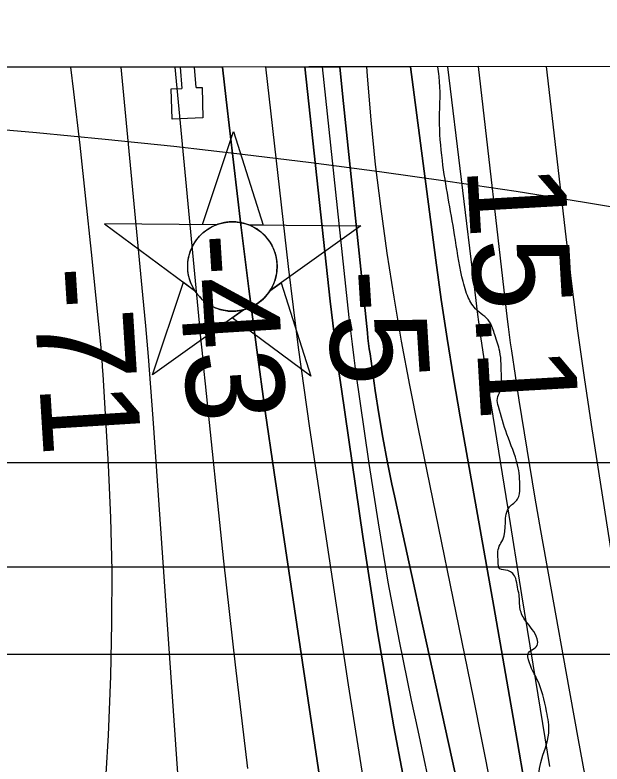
# Model space of a CAD drawing. Extents: x 3313447 to 3351316, y 703786 to 729172.
# Drawn here: x 3324497 to 3324898, y 726885 to 727397 of the extents above; entities that cross this region are included whole.
import ezdxf

# ---------------------------------------------------------------- set-up
doc = ezdxf.new("R2010")
doc.units = 0
for name, color, linetype in [('V-CHAN-DOCK', 7, 'Continuous'), ('V-CHAN-NAID', 7, 'Continuous'), ('V-GRID-FRAM', 7, 'Continuous'), ('V-RIVR-EDGE', 7, 'Continuous'), ('V-RIVR-RANG', 7, 'Continuous'), ('V-TOPO-DPTH', 7, 'Continuous'), ('V-TOPO-MAJR', 7, 'Continuous'), ('V-TOPO-MINR', 7, 'Continuous'), ('V-TOPO-WATR', 7, 'Continuous'), ('V-UTIL-LINE', 7, 'Continuous')]:
    doc.layers.add(name, color=color, linetype=linetype)

msp = doc.modelspace()

# ---------------------------------------------------------------- linework, layer by layer
at = {"layer": 'V-CHAN-DOCK'}
for p, q in [((3324610.23, 727361.24), (3324611.3, 727346.68)), ((3324621.03, 727347.18), (3324619.99, 727361.25)), ((3324604.09, 727346.31), (3324611.3, 727346.68)), ((3324604.6, 727325.6), (3324604.09, 727346.31)), ((3324621.03, 727347.18), (3324625.08, 727347.38)), ((3324625.08, 727347.38), (3324625.59, 727326.67)), ((3324625.59, 727326.67), (3324604.6, 727325.6))]:
    msp.add_line(p, q, dxfattribs=at)
at = {"layer": 'V-CHAN-NAID'}
for points in [[(3324634.94, 727253.57), (3324625.36, 727253.63), (3324646.48, 727317.12), (3324666.71, 727253.34), (3324657.12, 727253.41), (3324655.54, 727253.99), (3324653.45, 727254.61), (3324651.41, 727255.06), (3324649.37, 727255.37), (3324648.21, 727255.48), (3324646.67, 727255.56), (3324644.95, 727255.56), (3324643.58, 727255.49), (3324641.67, 727255.29), (3324640.31, 727255.07), (3324638.52, 727254.68), (3324636.99, 727254.26), (3324635.96, 727253.93)], [(3324634.94, 727253.57), (3324558.45, 727254.11), (3324620.02, 727208.71), (3324618.91, 727210.62), (3324618.1, 727212.25), (3324617.27, 727214.21), (3324616.57, 727216.27), (3324616.21, 727217.59), (3324615.85, 727219.22), (3324615.6, 727220.66), (3324615.42, 727222.26), (3324615.31, 727224), (3324615.3, 727225.58), (3324615.4, 727227.65), (3324615.59, 727229.27), (3324615.98, 727231.47), (3324616.46, 727233.39), (3324617.06, 727235.28), (3324617.72, 727236.96), (3324618.44, 727238.55), (3324619.26, 727240.08), (3324620.32, 727241.82), (3324621.35, 727243.29), (3324622.35, 727244.56), (3324623.35, 727245.71), (3324624.66, 727247.04), (3324625.71, 727248.01), (3324627.43, 727249.4), (3324628.64, 727250.27), (3324630.33, 727251.34), (3324632.06, 727252.29), (3324633.5, 727252.97)], [(3324657.12, 727253.41), (3324733.61, 727252.87), (3324671.41, 727208.34), (3324672.32, 727209.83), (3324673.3, 727211.68), (3324674.01, 727213.26), (3324674.75, 727215.22), (3324675.3, 727217), (3324675.7, 727218.64), (3324676.06, 727220.65), (3324676.24, 727222.23), (3324676.37, 727224.43), (3324676.34, 727226.49), (3324676.15, 727228.71), (3324675.88, 727230.47), (3324675.39, 727232.7), (3324674.75, 727234.84), (3324674, 727236.83), (3324673.35, 727238.27), (3324672.35, 727240.19), (3324671.28, 727241.91), (3324670.07, 727243.61), (3324668.81, 727245.15), (3324667.54, 727246.51), (3324665.91, 727248.05), (3324664.16, 727249.46), (3324662.48, 727250.64), (3324660.59, 727251.77), (3324659.12, 727252.53)], [(3324653.38, 727195.44), (3324591.18, 727150.92), (3324612.3, 727214.4), (3324620.02, 727208.71), (3324620.65, 727207.74), (3324622.04, 727205.89), (3324623.25, 727204.47), (3324624.72, 727202.97), (3324626.1, 727201.72), (3324627.56, 727200.56), (3324628.96, 727199.57), (3324630.64, 727198.54), (3324632.35, 727197.63), (3324634.14, 727196.81), (3324635.59, 727196.26), (3324637.22, 727195.73), (3324639.44, 727195.17), (3324640.98, 727194.88), (3324643, 727194.62), (3324644.54, 727194.52), (3324646.4, 727194.5), (3324648.09, 727194.57), (3324649.8, 727194.75), (3324651.7, 727195.06)], [(3324671.41, 727208.34), (3324679.21, 727213.92), (3324699.43, 727150.15), (3324645.58, 727189.86), (3324653.38, 727195.44), (3324655.04, 727195.91), (3324656.66, 727196.47), (3324658.81, 727197.39), (3324660.55, 727198.27), (3324662.42, 727199.39), (3324664.15, 727200.6), (3324665.71, 727201.84), (3324666.99, 727203.01), (3324668.38, 727204.43), (3324669.58, 727205.83), (3324670.7, 727207.3)]]:
    msp.add_lwpolyline(points, close=True, dxfattribs=at)
msp.add_circle((3324645.83, 727225.03), 30.54, dxfattribs=at)
at = {"layer": 'V-GRID-FRAM'}
msp.add_lwpolyline([(3317576.91, 727351.01), (3317595.43, 709166.01), (3349105.76, 709211.84), (3349071.38, 727396.82), (3317576.91, 727351.01)], dxfattribs=at)
at = {"layer": 'V-RIVR-EDGE'}
msp.add_spline([(3325128.87, 723979.74), (3325130.86, 724002.62), (3325129.36, 724023.95), (3325130.2, 724049.16), (3325132.57, 724063.89), (3325132.59, 724075.13), (3325133.05, 724103.44), (3325133.48, 724121.67), (3325133.91, 724137.18), (3325133.21, 724168.98), (3325130.96, 724198.07), (3325127.51, 724215.53), (3325123.67, 724232.22), (3325122.55, 724248.12), (3325122.61, 724270.61), (3325119.95, 724295.82), (3325118.07, 724318.71), (3325113.49, 724348.19), (3325109.62, 724353.24), (3325108.47, 724357.13), (3325113.52, 724362.15), (3325113.54, 724367.58), (3325107.79, 724394.74), (3325101.65, 724423.46), (3325093.21, 724459.16), (3325088.22, 724479.72), (3325085.57, 724505.32), (3325081.83, 724561.56), (3325078.43, 724596.09), (3325065.73, 724636.45), (3325059.19, 724658.57), (3325056.89, 724670.99), (3325053.43, 724682.24), (3325053.46, 724693.87), (3325057.76, 724707.44), (3325061.28, 724721.78), (3325070.21, 724724.08), (3325076.03, 724725.62), (3325080.31, 724732.98), (3325086.54, 724740.33), (3325091.62, 724755.83), (3325097.48, 724775.2), (3325101.02, 724793.03), (3325102.29, 724836.47), (3325108.59, 724877.17), (3325112.52, 724897.71), (3325114.88, 724911.28), (3325115.31, 724927.18), (3325108.05, 724971.79), (3325103.09, 725004.38), (3325096.97, 725038.52), (3325094.7, 725060.63), (3325092.8, 725076.15), (3325091.36, 725123.08), (3325085.2, 725138.22), (3325079.8, 725152.58), (3325077.53, 725173.14), (3325077.94, 725185.16), (3325081.46, 725196.01), (3325081.87, 725202.99), (3325081.52, 725221.6), (3325081.56, 725235.18), (3325076.93, 725247.6), (3325076.95, 725255.74), (3325073.9, 725274.36), (3325073.56, 725294.14), (3325072.8, 725300.35), (3325066.61, 725305.02), (3325061.57, 725307.36), (3325056.93, 725312.41), (3325056.16, 725315.52), (3325058.89, 725319.77), (3325063.16, 725321.7), (3325064.33, 725325.97), (3325062.41, 725333.34), (3325051.96, 725343.45), (3325044.62, 725354.32), (3325040.39, 725367.91), (3325037.73, 725388.47), (3325034.69, 725415.23), (3325032.81, 725437.34), (3325028.98, 725457.52), (3325022.42, 725471.88), (3325019.34, 725480.81), (3325019.76, 725495.16), (3325021.34, 725506.4), (3325027.58, 725521.51), (3325028.39, 725531.59), (3325027.65, 725549.82), (3325028.07, 725560.68), (3325030.05, 725576.96), (3325030.08, 725587.82), (3325026.6, 725594.81), (3325021.19, 725600.64), (3325015.79, 725611.9), (3325011.95, 725627.42), (3325013.54, 725643.31), (3325023.68, 725668.5), (3325024.5, 725685.17), (3325023.37, 725697.2), (3325016.8, 725707.68), (3324999.38, 725722.07), (3324999.41, 725730.99), (3325002.15, 725743.01), (3325009.93, 725753.85), (3325016.55, 725764.3), (3325016.96, 725772.06), (3325016.99, 725783.3), (3325013.15, 725802.31), (3325012.8, 725817.05), (3325005.46, 725827.93), (3325004.7, 725833.75), (3325008.98, 725840.72), (3325012.11, 725849.63), (3325012.14, 725863.2), (3325003.65, 725879.9), (3324999.04, 725896.59), (3325000.61, 725905.5), (3325006.06, 725911.31), (3325008.78, 725917.12), (3325006.12, 725937.29), (3325004.99, 725950.09), (3325001.13, 725959.4), (3325001.15, 725965.22), (3325001.18, 725978.41), (3325005.09, 725992.36), (3325004.34, 726001.28), (3324992.73, 726012.55), (3324990.42, 726019.15), (3324986.56, 726026.14), (3324982.31, 726030.03), (3324979.62, 726042.84), (3324975.01, 726059.13), (3324969.23, 726074.27), (3324966.94, 726089.4), (3324966.61, 726112.67), (3324968.99, 726135.55), (3324970.94, 726137.48), (3324975.98, 726139.02), (3324973.68, 726149.88), (3324968.29, 726163.86), (3324967.16, 726178.6), (3324967.18, 726188.29), (3324970.31, 726198.76), (3324976.55, 726212.7), (3324976.18, 726217.74), (3324970.77, 726224.74), (3324957.61, 726236.79), (3324946.4, 726251.17), (3324941.4, 726267.47), (3324940.65, 726280.27), (3324944.57, 726295.38), (3324950.04, 726310.49), (3324952.41, 726330.26), (3324947.44, 726358.2), (3324938.56, 726373.35), (3324932.39, 726388.48), (3324925.06, 726405.57), (3324920.86, 726429.23), (3324918.6, 726458.32), (3324919.04, 726480.04), (3324922.18, 726492.83), (3324928.02, 726504.45), (3324929.21, 726515.3), (3324925.75, 726525.4), (3324920.34, 726533.17), (3324911.44, 726540.94), (3324898.65, 726546.4), (3324898.27, 726549.51), (3324904.11, 726556.86), (3324904.12, 726561.51), (3324900.3, 726584.79), (3324894.17, 726616.61), (3324886.87, 726644.55), (3324883.07, 726672.48), (3324880.42, 726698.86), (3324875.46, 726733.38), (3324872.42, 726758.21), (3324873.62, 726772.56), (3324869.79, 726791.95), (3324865.97, 726817.17), (3324860.21, 726840.84), (3324856.37, 726855.2), (3324854.85, 726866.45), (3324854.86, 726869.94), (3324856.45, 726886.22), (3324861.93, 726906.38), (3324860.41, 726921.12), (3324853.87, 726943.24), (3324847.71, 726958.38), (3324847.71, 726960.32), (3324853.93, 726966.12), (3324853.94, 726970.77), (3324846.22, 726982.81), (3324842.36, 726990.97), (3324841.61, 727000.66), (3324840.46, 727006.09), (3324839.31, 727011.91), (3324833.89, 727017.36), (3324828.47, 727018.53), (3324827.31, 727023.58), (3324828.12, 727034.05), (3324830.45, 727038.31), (3324835.16, 727060.79), (3324840.61, 727066.2), (3324842.18, 727073.96), (3324840.66, 727089.47), (3324833.35, 727110.43), (3324827.58, 727129.45), (3324826.81, 727134.88), (3324828.77, 727139.92), (3324829.55, 727143.4), (3324829.57, 727149.61), (3324828.44, 727167.06), (3324824.98, 727178.32), (3324821.51, 727187.25), (3324811.84, 727196.19), (3324806.43, 727205.12), (3324802.59, 727217.93), (3324797.62, 727246.64), (3324789.21, 727297.46), (3324787.34, 727325.78), (3324787.03, 727354.86), (3324786.03, 727361.49)], degree=3, dxfattribs=at)
at = {"layer": 'V-TOPO-DPTH'}
for points in [[(3324639.14, 727361.28), (3323436.82, 727359.53), (3323417.71, 727093.55), (3323417.63, 727078.14), (3323417.58, 727062.73), (3323417.14, 726804.64)], [(3324668.62, 727361.32), (3324639.14, 727361.28), (3324641.56, 727339.16), (3324646.47, 727296.33), (3324651.51, 727253.51), (3324651.73, 727251.72), (3324656.95, 727209.84), (3324662.41, 727167.99), (3324668.23, 727126.19), (3324674.27, 727084.41), (3324746.92, 726597.31)], [(3324746.92, 726597.31), (3324674.27, 727084.41), (3324668.23, 727126.19), (3324662.41, 727167.99), (3324656.95, 727209.84), (3324651.73, 727251.72), (3324651.51, 727253.51), (3324646.47, 727296.33), (3324641.56, 727339.16), (3324639.14, 727361.28)], [(3324743.28, 726824.2), (3324725.14, 726939.25), (3324698.75, 727114.51), (3324694.76, 727142.09), (3324690.95, 727169.69), (3324687.45, 727197.33), (3324684.15, 727225), (3324668.62, 727361.32), (3324695.18, 727361.36)], [(3324743.28, 726824.2), (3324725.14, 726939.25), (3324698.75, 727114.51), (3324694.76, 727142.09), (3324690.95, 727169.69), (3324687.45, 727197.33), (3324684.15, 727225), (3324668.62, 727361.32)], [(3324768.3, 726845.89), (3324756.01, 726910.62), (3324745.01, 726975.58), (3324734.86, 727040.69), (3324720.23, 727141.18), (3324718.13, 727156.17), (3324716.13, 727171.18), (3324714.31, 727186.21), (3324712.59, 727201.25), (3324695.18, 727361.36), (3324719.21, 727361.4)], [(3324695.18, 727361.36), (3324712.59, 727201.25), (3324714.31, 727186.21), (3324716.13, 727171.18), (3324718.13, 727156.17), (3324720.23, 727141.18), (3324734.86, 727040.69), (3324745.01, 726975.58), (3324756.01, 726910.62), (3324768.3, 726845.89)], [(3324767.43, 727361.47), (3324719.21, 727361.4), (3324721.26, 727340.68), (3324738.02, 727179.8), (3324738.42, 727176.16), (3324738.85, 727172.52), (3324739.32, 727168.89), (3324739.82, 727165.26), (3324743.39, 727140.36), (3324745.87, 727124.32), (3324748.56, 727108.31), (3324751.58, 727092.36), (3324754.82, 727076.45), (3324756.55, 727068.36), (3324760.84, 727048.44), (3324765.14, 727028.53), (3324769.48, 727008.62), (3324773.84, 726988.71), (3324821.63, 726771.12)], [(3324719.21, 727361.4), (3324721.26, 727340.68), (3324738.02, 727179.8), (3324738.42, 727176.16), (3324738.85, 727172.52), (3324739.32, 727168.89), (3324739.82, 727165.26), (3324743.39, 727140.36), (3324745.87, 727124.32), (3324748.56, 727108.31), (3324751.58, 727092.36), (3324754.82, 727076.45), (3324756.55, 727068.36), (3324760.84, 727048.44), (3324765.14, 727028.53), (3324769.48, 727008.62), (3324773.84, 726988.71), (3324821.63, 726771.12)], [(3324890.83, 726854.79), (3324882.32, 726901.62), (3324873.85, 726948.46), (3324865.41, 726995.31), (3324856.56, 727044.59), (3324852.66, 727066.81), (3324848.87, 727089.06), (3324845.26, 727111.34), (3324841.77, 727133.63), (3324836.62, 727167.42), (3324835.82, 727172.84), (3324835.06, 727178.27), (3324834.37, 727183.71), (3324833.71, 727189.15), (3324813.84, 727361.53), (3324767.43, 727361.47)], [(3324856.14, 726809.68), (3324840.39, 726901.23), (3324824.35, 726992.74), (3324801.33, 727122.36), (3324796.77, 727149.05), (3324792.46, 727175.78), (3324788.51, 727202.56), (3324784.8, 727229.37), (3324767.43, 727361.47)], [(3324767.43, 727361.47), (3324784.8, 727229.37), (3324788.51, 727202.56), (3324792.46, 727175.78), (3324796.77, 727149.05), (3324801.33, 727122.36), (3324824.35, 726992.74), (3324840.39, 726901.23), (3324856.14, 726809.68)]]:
    msp.add_lwpolyline(points, dxfattribs=at)
at = {"layer": 'V-TOPO-MAJR'}
msp.add_lwpolyline([(3324656.32, 726882.04), (3324647.84, 726952.87), (3324640, 727023.78), (3324627.47, 727144.84), (3324626.4, 727155.28), (3324625.35, 727165.73), (3324624.33, 727176.18), (3324623.32, 727186.63), (3324606.72, 727361.23)], dxfattribs=at)
at = {"layer": 'V-TOPO-MINR'}
for points in [[(3324558.09, 726852.06), (3324561.14, 726904.95), (3324562.66, 726945.22), (3324563.5, 726981.3), (3324563.64, 727017.39), (3324562.74, 727053.46), (3324561.14, 727089.52), (3324557.5, 727151.2), (3324557.16, 727156.41), (3324556.78, 727161.63), (3324556.33, 727166.83), (3324555.84, 727172.04), (3324549.51, 727234.76), (3324545.69, 727271.31), (3324541.72, 727307.84), (3324537.49, 727344.35), (3324535.47, 727361.13)], [(3324625.76, 726630.08), (3324591.64, 727121.31), (3324590.09, 727142.42), (3324588.43, 727163.51), (3324586.6, 727184.6), (3324584.67, 727205.67), (3324569.77, 727361.18)], [(3324639.14, 727361.28), (3324641.56, 727339.16), (3324646.47, 727296.33), (3324651.51, 727253.51), (3324651.73, 727251.72), (3324656.95, 727209.84), (3324662.41, 727167.99), (3324668.23, 727126.19), (3324674.27, 727084.41), (3324746.92, 726597.31)], [(3324743.28, 726824.2), (3324725.14, 726939.25), (3324698.75, 727114.51), (3324694.76, 727142.09), (3324690.95, 727169.69), (3324687.45, 727197.33), (3324684.15, 727225), (3324668.62, 727361.32)], [(3324768.3, 726845.89), (3324756.01, 726910.62), (3324745.01, 726975.58), (3324734.86, 727040.69), (3324720.23, 727141.18), (3324718.13, 727156.17), (3324716.13, 727171.18), (3324714.31, 727186.21), (3324712.59, 727201.25), (3324695.18, 727361.36)], [(3324783.45, 726857.56), (3324772.59, 726908.11), (3324768.14, 726928.89), (3324759.95, 726969.13), (3324752.32, 727009.47), (3324745.52, 727049.95), (3324739.27, 727090.53), (3324730.23, 727153.51), (3324728.97, 727162.68), (3324727.77, 727171.87), (3324726.67, 727181.06), (3324725.64, 727190.26), (3324707.42, 727361.38)], [(3324821.63, 726771.12), (3324773.84, 726988.71), (3324769.48, 727008.62), (3324765.14, 727028.53), (3324760.84, 727048.44), (3324756.55, 727068.36), (3324754.82, 727076.45), (3324751.58, 727092.36), (3324748.56, 727108.31), (3324745.87, 727124.32), (3324743.39, 727140.36), (3324739.82, 727165.26), (3324739.32, 727168.89), (3324738.85, 727172.52), (3324738.42, 727176.16), (3324738.02, 727179.8), (3324721.26, 727340.68), (3324719.21, 727361.4)], [(3324834.64, 726808.99), (3324810.51, 726930.7), (3324772.82, 727114.06), (3324766.93, 727143.98), (3324761.36, 727173.96), (3324756.28, 727204.02), (3324751.53, 727234.15), (3324747.36, 727264.35), (3324743.66, 727294.61), (3324740.64, 727324.94), (3324738.08, 727355.33), (3324737.64, 727361.42)], [(3324862.74, 726883.43), (3324853.11, 726942.14), (3324843.58, 727000.86), (3324834.11, 727059.6), (3324820.15, 727146.8), (3324817.81, 727161.95), (3324815.58, 727177.12), (3324813.53, 727192.32), (3324811.6, 727207.53), (3324792.89, 727361.5)], [(3324890.83, 726854.79), (3324882.32, 726901.62), (3324873.85, 726948.46), (3324865.41, 726995.31), (3324856.56, 727044.59), (3324852.66, 727066.81), (3324848.87, 727089.06), (3324845.26, 727111.34), (3324841.77, 727133.63), (3324836.62, 727167.42), (3324835.82, 727172.84), (3324835.06, 727178.27), (3324834.37, 727183.71), (3324833.71, 727189.15), (3324813.84, 727361.53)], [(3324942.15, 726788.21), (3324924, 726906.91), (3324891.18, 727117.16), (3324886.39, 727149.12), (3324881.86, 727181.11), (3324877.71, 727213.15), (3324873.82, 727245.23), (3324860.42, 727361.6)]]:
    msp.add_lwpolyline(points, dxfattribs=at)
at = {"layer": 'V-TOPO-WATR'}
msp.add_lwpolyline([(3324856.14, 726809.68), (3324840.39, 726901.23), (3324824.35, 726992.74), (3324801.33, 727122.36), (3324796.77, 727149.05), (3324792.46, 727175.78), (3324788.51, 727202.56), (3324784.8, 727229.37), (3324767.43, 727361.47)], dxfattribs=at)
at = {"layer": 'V-UTIL-LINE'}
for p, q in [((3321087.57, 727091.13), (3325881, 727091.13)), ((3321075.68, 727019.77), (3325928.58, 727019.77)), ((3321111.36, 726960.3), (3325857.22, 726960.3))]:
    msp.add_line(p, q, dxfattribs=at)
msp.add_lwpolyline([(3324464.9, 727320.66), (3324511.91, 727316.55), (3324558.88, 727312.04), (3324605.8, 727307.12), (3324652.69, 727301.79), (3324699.52, 727296.06), (3324746.31, 727289.92), (3324793.03, 727283.37), (3324839.7, 727276.42), (3324886.31, 727269.07), (3324932.85, 727261.31), (3324979.33, 727253.15), (3325025.73, 727244.58), (3325072.05, 727235.61), (3325118.29, 727226.25), (3325164.46, 727216.48), (3325210.53, 727206.31), (3325256.52, 727195.74), (3325302.41, 727184.77), (3325348.21, 727173.41)], dxfattribs=at)

# ---------------------------------------------------------------- texts
at = {"layer": 'V-RIVR-RANG'}
for s, rotation, p in [('15.1', 273.2783, (3324805.81, 727293.13)), ('-43', 273.5618, (3324607.77, 727246.25)), ('-71', 273.5618, (3324508.98, 727223.7)), ('-5', 273.5618, (3324709.49, 727221.68))]:
    msp.add_text(s, height=67, rotation=rotation, dxfattribs=at).set_placement(p)

doc.saveas('drawing.dxf')
